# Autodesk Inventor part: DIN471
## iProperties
Comments: To add or edit properties for Autodesk Inventor files, use iProperties.
Created: 2003-08
Part Number: DIN471
Vendor: Autodesk Inc.
Document SubType Name: Modeling
Designer: FranzK
Material: Default
Description: Spring Retaining Ring
Standard: DIN 471
Manufacturer: Standard
Standards Organization: Custom
Alert: To add or edit properties for Autodesk Inventor files, use iProperties.
Control State: 0
Master: False
Checked Out: False
Shininess: 64.0
Length Units: 11269
Angle Units: 11279
Time Units: 11290
Mass Units: 11283
Length Display Precision: 3
Angle Display Precision: 2
Compacted: True
Density: 0.0
Volumn: 0.0
Area: 0.0
PropertySet Name: Model Information
Author: FranzK
Revision Number: 5
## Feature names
1. Body [Extrusion]
